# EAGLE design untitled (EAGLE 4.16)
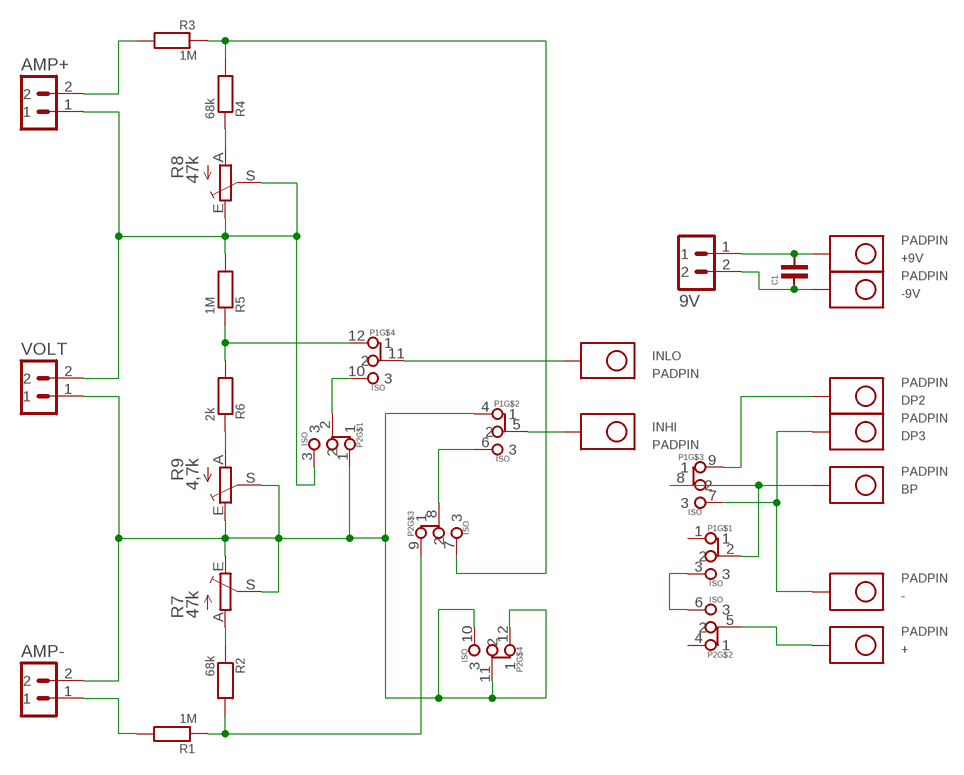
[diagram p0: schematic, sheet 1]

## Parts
9V  MA02-1  [MA02-1]
+  PADPIN  [PAD]
+9V  PADPIN  [PAD]
-  PADPIN  [PAD]
-9V  PADPIN  [PAD]
AMP+  MA02-1  [MA02-1]
AMP-  MA02-1  [MA02-1]
BP  PADPIN  [PAD]
C1  CAP  [CAP]
DP2  PADPIN  [PAD]
DP3  PADPIN  [PAD]
INHI  PADPIN  [PAD]
INLO  PADPIN  [PAD]
P1  ISO  [ISOSTAT]
P2  ISO  [ISOSTAT]
R1  1M  RES  [RES]
R2  68k  RES  [RES]
R3  1M  RES  [RES]
R4  68k  RES  [RES]
R5  1M  RES  [RES]
R6  2k  RES  [RES]
R7  47k  TRIM_EU-CA6V  [CA6V]
R8  47k  TRIM_EU-CA6V  [CA6V]
R9  4,7k  TRIM_EU-CA6V  [CA6V]
VOLT  MA02-1  [MA02-1]

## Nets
N$1: R2.P$1 R7.A
N$2: R4.P$1 R8.A
N$3: R6.P$1 R9.A
N$4: P2.9 R1.P$1 R2.P$2
N$5: P2.7 R3.P$1 R4.P$2
N$6: AMP-.2 P1.4 P2.1 P2.10 P2.11 P2.12 R7.E R7.S R9.E R9.S VOLT.1
N$7: P1.12 R5.P$1 R6.P$2
N$8: AMP+.1 P2.3 R5.P$2 R8.E R8.S VOLT.2
N$9: INLO.P$1 P1.11
N$10: AMP+.2 R3.P$2
N$11: INHI.P$1 P1.5
N$12: P1.10 P2.2
N$13: AMP-.1 R1.P$2
N$14: P1.6 P2.8
N$15: 9V.2 -9V.P$1 C1.P$1
N$16: 9V.1 +9V.P$1 C1.P$2
N$17: BP.P$1 P1.2 P1.8
N$18: -.P$1 DP3.P$1 P1.7
N$19: DP2.P$1 P1.9
N$21: +.P$1 P2.5
N$25: P1.3 P2.6
Unconnected: P1.1 P2.4

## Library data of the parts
9V AMP+ AMP- VOLT = divers:MA02-1: PIN HEADER
+ +9V - -9V BP DP2 DP3 INHI INLO = pady:PADPIN
C1 = opory:CAP
P1 P2 = isostat:ISO
R1-R6 = opory:RES
R7-R9 = pot:TRIM_EU-: POTENTIOMETER

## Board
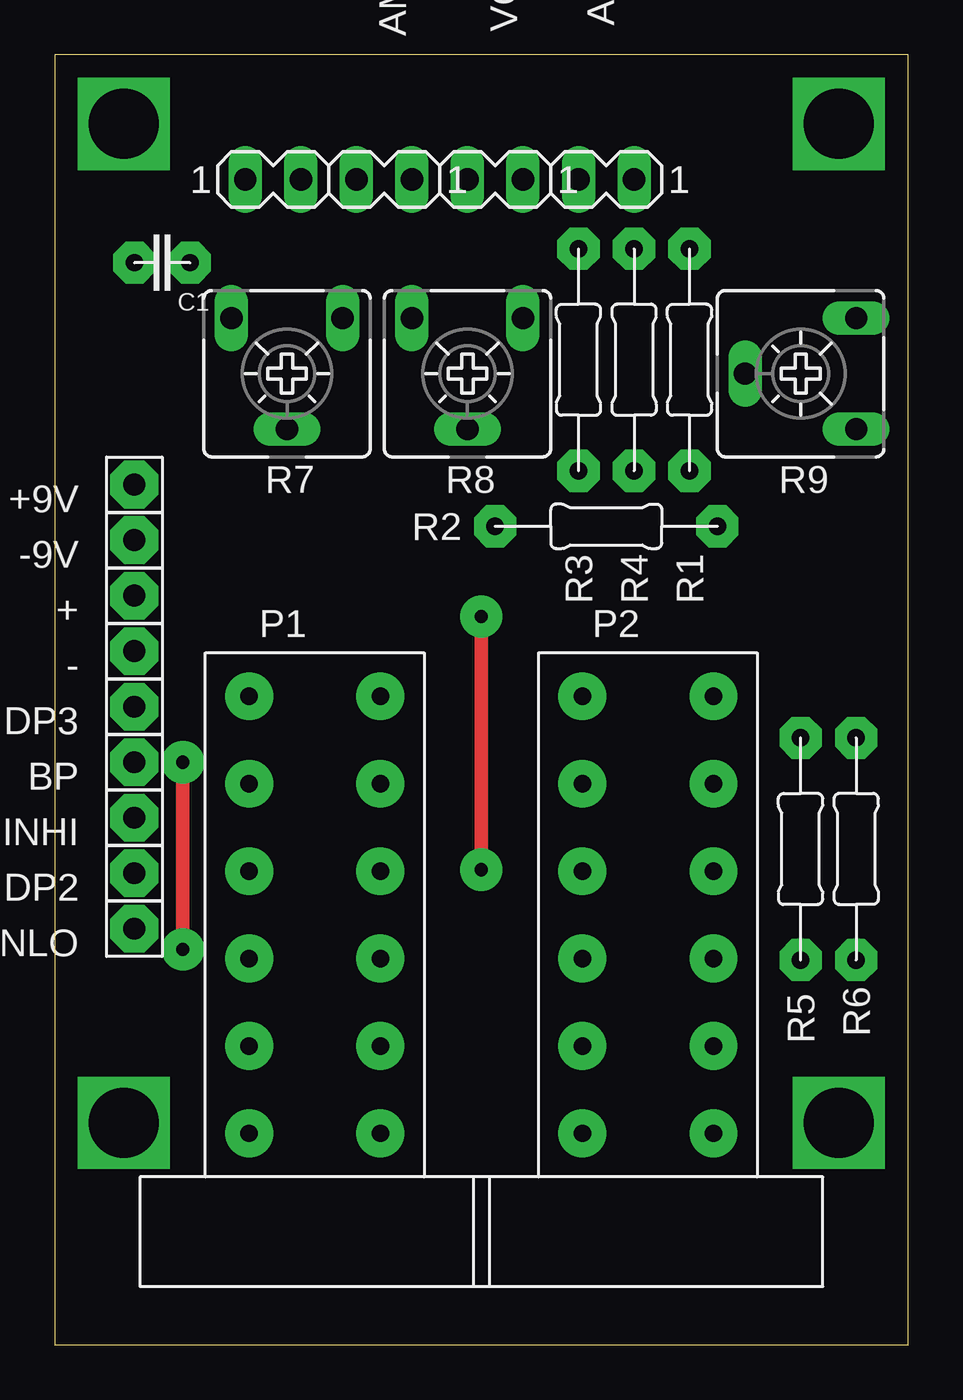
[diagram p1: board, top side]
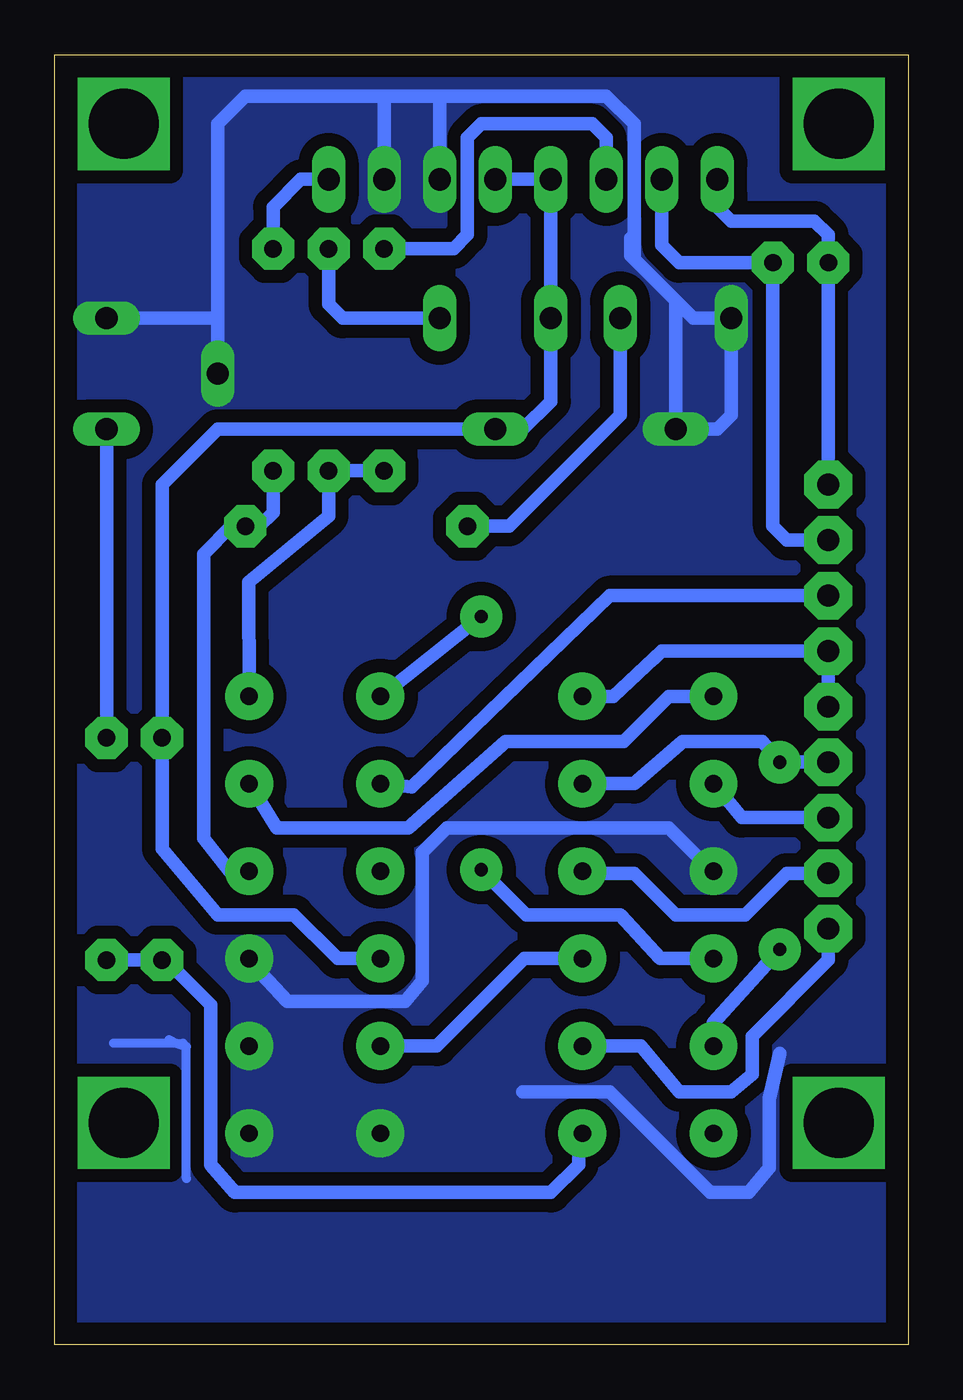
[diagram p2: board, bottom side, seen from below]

Size 39.04 x 59.05 mm. Coordinates in mm from the lower left corner, seen from the top.
Outline: 0,0 39.04,0 39.04,59.05 0,59.05 0,0
Copper layers (1*16): Top 0.035mm / dielectric 1.5mm / Bottom 0.035mm
Design rules "default": minimum track width 10mil, minimum drill 24mil, track to track 8mil, track to pad 8mil, pad to pad 8mil, via to via 8mil, smd to smd 8mil, copper to edge 40mil, drill to drill 8mil, minimum pad ring 10mil, minimum via ring 8mil, stop-mask expansion 4mil, vias tented up to drill 0mil, thermal gap 10mil

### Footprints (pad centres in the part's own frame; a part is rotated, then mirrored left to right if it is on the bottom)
MA02-1 = drill 1.016 long: 1 -2.54,0; 2 0,0
PAD = drill 1 pad 2.184 octagon: P$1 0,0
CAP = drill 0.8 pad 1.93 octagon: P$1 -1.27,0; P$2 1.27,0
ISOSTAT = drill 0.8 pad 2.184 round: 1 -3,-10; 2 -3,-6; 3 -3,-2; 4 -3,2; 5 -3,6; 6 -3,10; 7 3,10; 8 3,6; 9 3,2; 10 3,-2; 11 3,-6; 12 3,-10
RES = drill 0.8 pad 1.93 octagon: P$1 -5.08,0; P$2 5.08,0
CA6V = drill 1.016 long: A -2.54,-2.54; E 2.54,-2.54; S 0,2.54

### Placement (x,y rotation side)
9V  11.27,53.34 0 top
+  3.64,34.28 90 top
+9V  3.64,39.37 90 top
-  3.64,31.74 90 top
-9V  3.64,36.83 90 top
AMP+  13.8,53.34 180 top
AMP-  23.96,53.34 180 top
BP  3.64,26.66 90 top
C1  4.91,49.52 180 top
DP2  3.64,21.59 90 top
DP3  3.64,29.2 90 top
INHI  3.64,24.12 90 top
INLO  3.64,19.05 90 top
P1  11.9,19.68 0 top
P2  27.14,19.68 0 top
R1  29.05,45.08 90 top
R2  25.23,37.46 0 top
R3  23.96,45.08 90 top
R4  26.51,45.08 270 top
R5  34.12,22.7 90 top
R6  36.66,22.7 270 top
R7  10.63,44.45 180 top
R8  18.88,44.45 180 top
R9  34.12,44.45 90 top
VOLT  18.88,53.34 180 top

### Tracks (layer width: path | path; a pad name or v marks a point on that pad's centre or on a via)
N$1
  Bottom 0.61: R7.A 13.17,42.54 18.25,37.46 R2.P$1
N$2
  Bottom 0.61: R8.A 25.87,46.98 26.51,47.62 R4.P$1
N$3
  Bottom 0.61: R6.P$1 R9.A
N$4
  Bottom 0.61: P2.9 31.05,21.68 32.22,23.17 32.22,36.19 30.95,37.46 R2.P$2 29.68,37.46 29.05,38.09 R1.P$1
N$5
  Bottom 0.61: P2.7 30.16,34.92 26.51,37.94 R4.P$2 R3.P$1
N$6
  Bottom 0.406: 33.01,7.62 33.01,13.65 33.49,13.81 | 33.49,13.81 33.17,13.81 | 33.49,13.81 36.35,13.81 | 33.49,13.81 33.81,13.96
  Bottom 0.61: 31.59,46.98 R9.E | 31.59,46.98 R9.S | 31.59,46.98 31.59,55.88 30.31,57.15 23.96,57.15 | 21.42,57.15 13.8,57.15 12.53,55.88 12.53,49.68 9.84,46.98 R7.E 8.09,42.54 8.72,41.91 R7.S 10.63,47.78 12.69,49.84 12.69,50.64 | 21.42,57.15 23.96,57.15 | 23.96,57.15 AMP-.2 | 21.42,57.15 VOLT.1 | P1.4 8.98,21.68 10.95,23.65 21.11,23.65 22.22,22.54 22.22,16.66 23.01,15.71 28.41,15.71 30.16,17.62 30.14,17.63 P2.10 | 5.87,13.33 6.34,11.27 6.34,8.09 7.3,6.98 9.04,6.98 13.65,11.58 17.62,11.58
  pour Bottom (isolate 0.61, no thermals): -0.48,59.69 39.84,59.69 39.84,-0.48 -0.64,-0.48 -0.64,59.69 -0.32,59.69
N$7
  Bottom 0.61: R6.P$2 R5.P$1 33.97,17.62 31.9,15.55 31.9,8.25 30.79,6.98 16.34,6.98 15.08,8.25 15.08,9.68 P1.12
N$8
  Bottom 0.61: VOLT.2 AMP+.1 R8.E 16.34,43.18 17.62,41.91 R8.S 31.59,41.91 34.12,39.37 R5.P$2 | 26.2,17.79 28.09,19.68 31.59,19.68 34.12,22.7 R5.P$2 | R5.P$2 33.97,27.94 | 26.2,17.79 | P2.3 26.09,17.68 26.2,17.79
N$9
  Bottom 0.61: P1.11 12.22,13.68 10.47,11.58 8.09,11.58 7.14,12.38 7.14,14.12 3.64,17.62 INLO.P$1
N$10
  Bottom 0.61: AMP+.2 13.8,55.24 14.44,55.88 19.52,55.88 20.16,55.24 20.16,50.8 20.79,50.16 R3.P$2
N$11
  Bottom 0.61: INHI.P$1 7.61,24.12 8.88,25.68 P1.5
N$12
  Bottom 0.61: P1.10 17.55,17.68 21.55,13.68 P2.2
N$13
  Bottom 0.61: AMP-.1 27.77,53.34 29.05,52.07 R1.P$2
N$14
  Bottom 0.61: P1.6 10.95,29.68 13.01,27.62 18.41,27.62 22.85,23.65 28.89,23.65 30.14,25.7 | 30.14,25.7 30.16,25.71 | 30.14,25.7 P2.8
N$15
  Bottom 0.61: 9V.2 11.27,50.32 10.47,49.52 C1.P$1 6.18,37.46 5.55,36.83 -9V.P$1
N$16
  Bottom 0.61: 9V.1 8.72,52.07 8.09,51.43 4.28,51.43 3.64,50.8 3.64,50.48 C1.P$2 +9V.P$1
N$17  (via drill 0.6 pad 1.93)
  Top 0.61: v5.87,18.09 v5.87,26.66
  Bottom 0.61: v5.87,26.66 6.01,26.84 | 6.01,26.84 6.66,27.62 10.31,27.62 12.53,25.68 P1.8 | P1.2 8.9,14.74 v5.87,18.09 | v5.87,26.66 BP.P$1 | v5.87,26.66 5.85,26.68 6.01,26.84 | v5.87,26.66
N$18
  Bottom 0.61: DP3.P$1 -.P$1 11.27,31.74 | P1.7 13.49,29.68 11.27,31.74 | 11.27,31.74 11.58,31.43
N$19
  Bottom 0.61: DP2.P$1 5.55,21.59 7.45,19.68 10.63,19.68 12.53,21.59 15.08,21.59 15.08,21.68 P1.9
N$20  (via drill 3.2 pad 3.81)
  other vias: 35.87,55.88
N$21
  Bottom 0.61: P2.5 22.71,25.54 13.65,34.28 +.P$1
N$22  (via drill 3.2 pad 3.81)
  other vias: 3.17,10.16
N$23  (via drill 3.2 pad 3.81)
  other vias: 3.17,55.88
N$24  (via drill 3.2 pad 3.81)
  other vias: 35.87,10.16
N$25  (via drill 0.6 pad 1.93)
  Top 0.61: v19.52,21.74 v19.52,33.33
  Bottom 0.61: P1.3 11.33,17.68 13.17,19.68 17.46,19.68 19.36,21.59 v19.52,21.74 | P2.6 24.12,29.68 v19.52,33.33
